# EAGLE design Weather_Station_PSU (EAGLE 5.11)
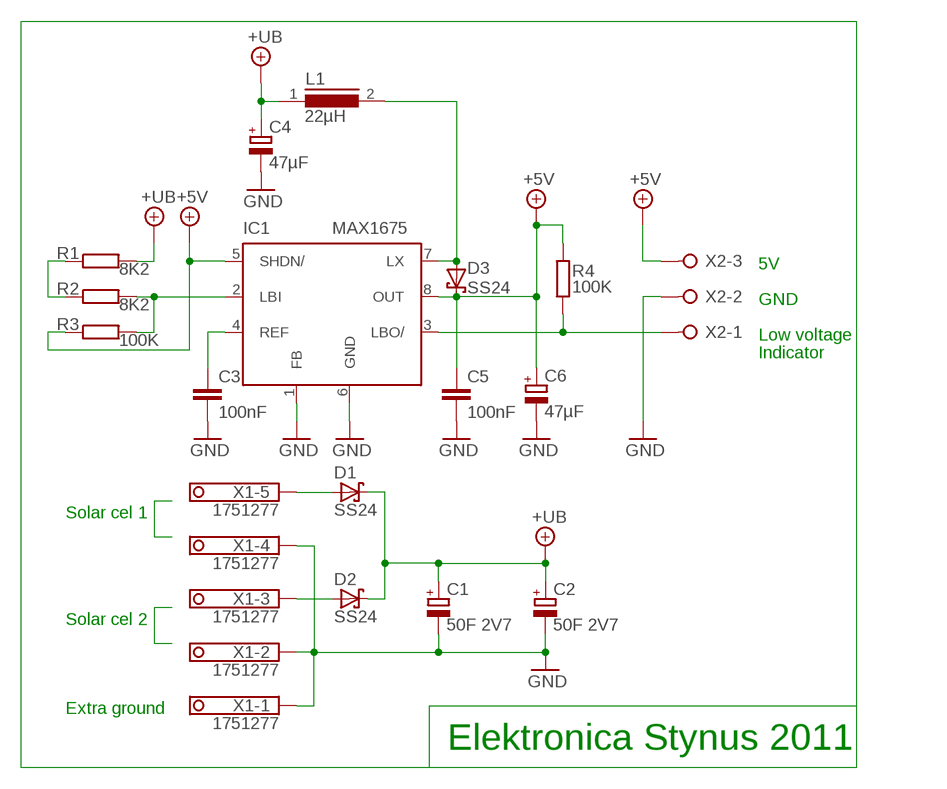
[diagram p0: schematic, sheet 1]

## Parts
C1  50F 2V7  CPOL-EUE7.5-18  [E7,5-18]
C2  50F 2V7  CPOL-EUE7.5-18  [E7,5-18]
C3  100nF  C-EUC0805  [C0805]
C4  47µF  CPOL-EUE2.5-6  [E2,5-6]
C5  100nF  C-EUC0805  [C0805]
C6  47µF  CPOL-EUE2.5-6  [E2,5-6]
D1  SS24  MBRS130LT3  [SMB]
D2  SS24  MBRS130LT3  [SMB]
D3  SS24  MBRS130LT3  [SMB]
IC1  MAX1675  MAX1674  [UMAX8]
L1  22µH  82114R  [82114R]
R1  8K2  R-EU_M0805  [M0805]
R2  8K2  R-EU_M0805  [M0805]
R3  100K  R-EU_M0805  [M0805]
R4  100K  R-EU_M0805  [M0805]
X1  1751277  [1751277]
X2  W237-3E  [W237-3E]

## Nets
+5V: C5.1 C6.+ D3.C IC1.5(SHDN/) IC1.8(OUT) R3.1 R4.2 X2.3
+UB: C1.+ C2.+ C4.+ D1.C D2.C L1.1 R1.2
GND: C1.- C2.- C3.2 C4.- C5.2 C6.- IC1.1(FB) IC1.6(GND) X1.1 X1.2 X1.4 X2.2
N$1: D3.A IC1.7(LX) L1.2
N$2: R1.1 R2.1
N$3: D1.A X1.5
N$4: IC1.2(LBI) R2.2 R3.2
N$5: D2.A X1.3
N$6: C3.1 IC1.4(REF)
N$9: IC1.3(LBO/) R4.1 X2.1

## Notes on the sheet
- 5V
- GND
- Low voltage
- Indicator
- Solar cel 1
- Solar cel 2
- Extra ground
- Elektronica Stynus 2011

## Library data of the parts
C1 C2 C4 C6 = rcl:CPOL-EU: POLARIZED CAPACITOR, European symbol
C3 C5 = rcl:C-EU: CAPACITOR, European symbol
D1-D3 = diode:MBRS130LT3: Schottky Power Rectifier
IC1 = maxim:MAX1674: DC/DC CONVERTER; MF: MAXIM; MPN: MAX1674EUA+; OC_FARNELL: 1379864; OC_NEWARK: 23K5719
L1 = inductors:82114R: INDUCTOR
R1-R4 = rcl:R-EU_: RESISTOR, European symbol
X1 = con-phoenix-350:1751277: MKDS 1/ 5-3,5 Printklemme Nennstrom: 10 A Bemessungsspannung: 160 V Raster: 3,5 mm Polzahl: 5 Montageart: Löten Anschlussart: Schraubanschluss Anschlussrichtung vom Leiter zur Platine: 0° Source: http://eshop.phoenixcontact.com .. 1751277.pdf; OC_FARNELL: unknown; OC_NEWARK: unknown
X2 = con-wago-508:W237-3E: WAGO SREW CLAMP; OC_FARNELL: unknown; OC_NEWARK: unknown

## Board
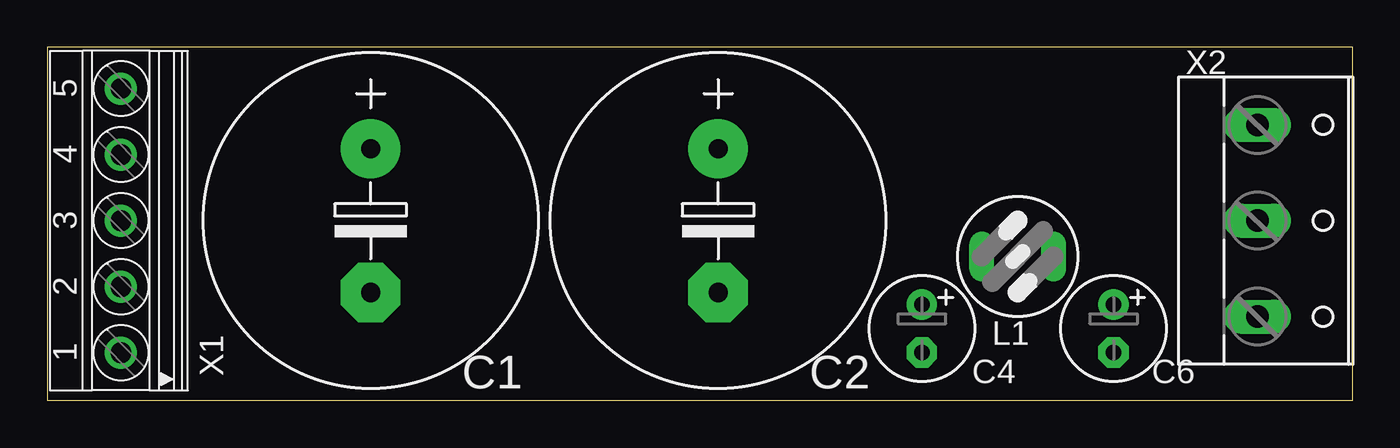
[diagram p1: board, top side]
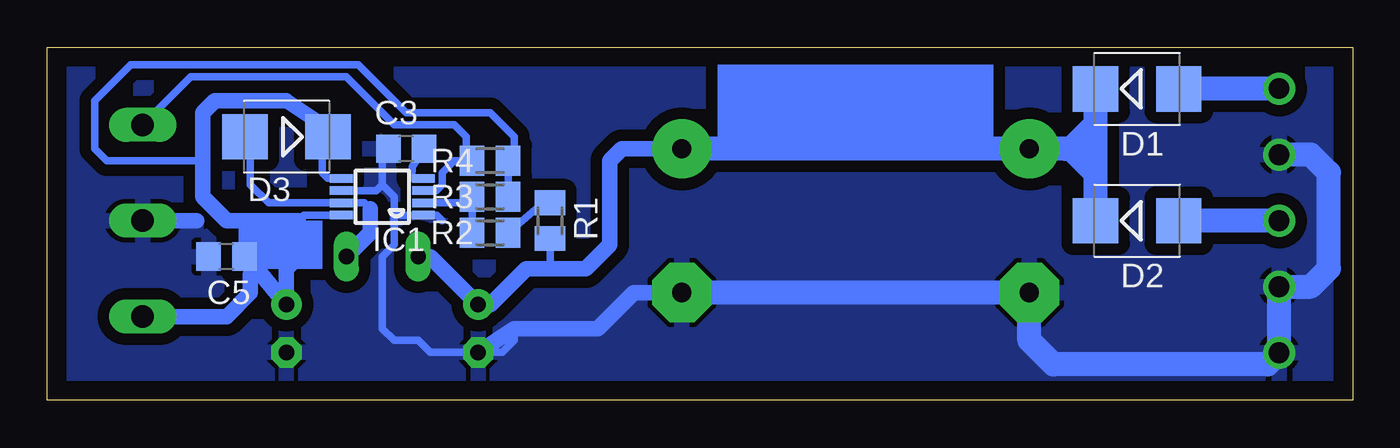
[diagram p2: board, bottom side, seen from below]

Size 69.19 x 18.72 mm. Coordinates in mm from the lower left corner, seen from the top.
Outline: 0,0 69.19,0 69.19,18.72 0,18.72 0,0
Copper layers (1*16): Top 0.035mm / dielectric 1.5mm / Bottom 0.035mm
Design rules "default": minimum track width 10mil, minimum drill 24mil, track to track 8mil, track to pad 8mil, pad to pad 8mil, via to via 8mil, smd to smd 8mil, copper to edge 40mil, drill to drill 8mil, minimum pad ring 10mil, minimum via ring 8mil, stop-mask expansion 4mil, vias tented up to drill 0mil, thermal gap 10mil

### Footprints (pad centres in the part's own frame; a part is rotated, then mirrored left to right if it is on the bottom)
E7,5-18 = drill 1.016 pad 3.15 round: + -3.81,0 | drill 1.016 pad 3.15 octagon: - 3.81,0
C0805 = smd 1.3 x 1.5: 1 -0.95,0; 2 0.95,0
E2,5-6 = drill 0.813 pad 1.6 round: + -1.27,0 | drill 0.813 pad 1.6 octagon: - 1.27,0
SMB = smd 2.4 x 2.4: A 2.2,0; C -2.2,0
UMAX8 = smd 0.45 x 1.2: 1 -0.975,-2.175; 2 -0.325,-2.175; 3 0.325,-2.175; 4 0.975,-2.175; 5 0.975,2.175; 6 0.325,2.175; 7 -0.325,2.175; 8 -0.975,2.175
82114R = drill 0.813 long: 1 0,1.905; 2 0,-1.905
M0805 = smd 1.3 x 1.6: 1 -0.95,0; 2 0.95,0
1751277 = drill 1.1 pad 1.7 round: 1 -7,-0.1; 2 -3.5,-0.1; 3 0,-0.1; 4 3.5,-0.1; 5 7,-0.1
W237-3E = drill 1.194 long: 1 -5.08,-0.635; 2 0,-0.635; 3 5.08,-0.635

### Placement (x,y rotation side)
C1  17.14,9.53 270 top
C2  35.56,9.53 270 top
C3  50.16,13.34 180 bottom
C4  46.35,3.81 270 top
C5  59.69,7.62 180 bottom
C6  56.52,3.81 270 top
D1  11.43,16.51 0 bottom
D2  11.43,9.53 0 bottom
D3  56.52,13.97 180 bottom
IC1  51.44,10.79 90 bottom
L1  51.44,7.62 90 top
R1  42.55,9.53 270 bottom
R2  45.72,8.89 180 bottom
R3  45.72,10.79 180 bottom
R4  45.72,12.7 0 bottom
X1  3.81,9.53 90 top
X2  64.77,9.53 270 top

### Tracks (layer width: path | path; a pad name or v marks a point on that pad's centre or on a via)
+5V
  Bottom 0.406: D3.C 53.98,13.63 54.61,14.61 54.61,12.06 54.31,11.77 IC1.5 | 60.96,15.24 60.96,12.7 66.04,12.7 66.67,13.34 66.67,15.88 64.77,17.78 52.7,17.78 50.16,15.24 45.72,15.24 44.45,13.97 44.45,13.02 R4.2 R3.1 | IC1.8 55.59,9.82 55.88,9.53
  Bottom 0.813: D3.C 53.98,13.68 | 54.61,14.61 56.52,15.88 60.33,15.88 60.96,15.24 60.96,10.79 59.69,9.53 55.88,9.53 55.88,7.62 56.52,6.99 C6.+ 58.1,6.99 | X2.3 59.69,4.45 58.42,5.71 58.42,6.67 58.1,6.99 | C5.1 58.1,6.99
+UB
  Bottom 0.406: 42.55,6.99 R1.2
  Bottom 0.813: L1.1 48.9,7.62 C4.+ 45.72,5.08 43.81,6.99 42.55,6.99 40.64,6.99 39.37,8.26 39.37,12.7 38.73,13.34 C2.+ | 13.97,14.61 15.24,13.34 13.97,12.06
  Bottom 1.27: C2.+ C1.+ 15.24,13.34 13.63,13.34 | D2.C 13.63,13.34 | 13.63,13.34 D1.C
GND
  Bottom 0.406: IC1.6 51.74,11.12 51.44,11.43 | 51.44,11.43 51.44,13.02 C3.2 | 48.26,9.53 48.55,9.82 IC1.1 50.46,9.82 50.8,10.16 | 50.8,10.16 50.8,10.79 51.44,11.43 | 50.8,10.16 50.8,8.26 51.44,7.62 51.44,3.81 50.8,3.17 49.53,3.17 48.9,2.54 45.09,2.54 44.45,3.17 44.45,3.81
  Bottom 0.813: 61.28,9.53 X2.2 | C2.- 38.1,5.71 40.01,3.81 44.45,3.81 C4.-
  Bottom 1.27: X1.4 2.23,13.03 1.27,12.06 1.27,6.99 2.23,6.03 X1.2 X1.1 4.53,1.91 15.88,1.91 17.14,3.17 C1.- C2.-
  pour Bottom (isolate 0.61): 0,18.41 69.22,18.41 69.22,0 0,0
N$1
  Bottom 0.406: 52.07,10.16 52.38,10.47 IC1.7 57.46,10.47 58.42,11.43 58.42,13.68 D3.A
  Bottom 0.813: 52.07,10.16 52.07,8.89 L1.2
N$2
  Bottom 0.406: R2.1 42.55,10.79 R1.1
N$3
  Bottom 1.27: X1.5 5.41,16.52 D1.A
N$4
  Bottom 0.406: IC1.2 46.99,10.47 R3.2 R2.2
N$5
  Bottom 1.27: X1.3 D2.A
N$6
  Bottom 0.406: IC1.4 49.87,11.77 49.85,12.38 C3.1
N$9
  Bottom 0.406: IC1.3 48.57,11.12 48.26,11.43 48.26,12.06 47.62,12.7 R4.1 46.99,13.02 46.99,13.97 47.62,14.61 50.8,14.61 53.34,17.14 61.59,17.14 X2.1
(copper drawn outside any net)
  shapes: Bottom area x2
